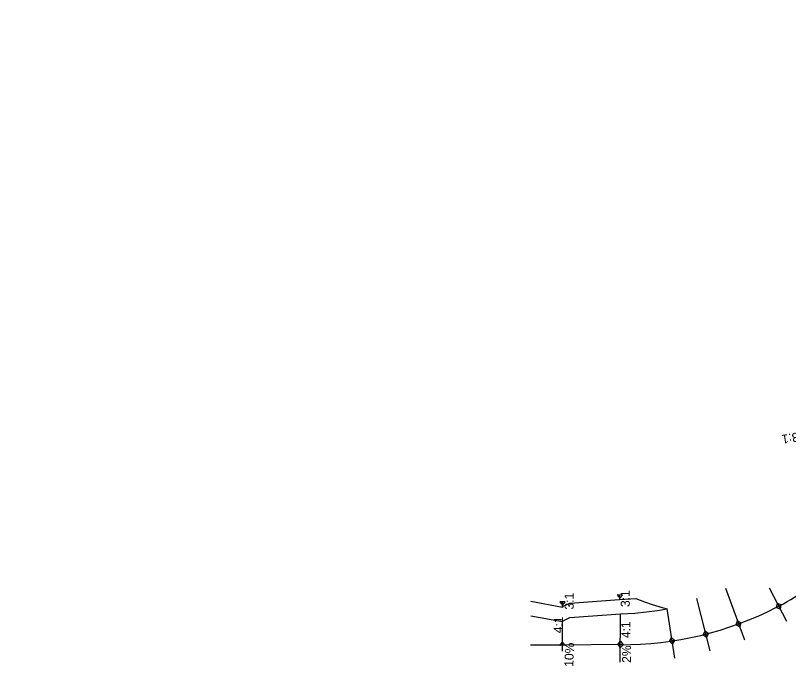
# Model space of a CAD drawing. Extents: x 2957411 to 5201395, y -5659629 to 3720102.
# Drawn here: x 5196292 to 5196826, y 3709360 to 3709819 of the extents above; entities that cross this region are included whole.
import ezdxf

# ---------------------------------------------------------------- set-up
doc = ezdxf.new("R2010")
doc.units = 0
for name, color, linetype in [('Default', 7, 'Continuous'), ('dsnProfileGradePropLine', 7, 'Continuous'), ('TES', 7, 'Continuous'), ('TL_Backslope', 7, 'Continuous')]:
    doc.layers.add(name, color=color, linetype=linetype)

msp = doc.modelspace()

# ---------------------------------------------------------------- linework, layer by layer
at = {"layer": 'dsnProfileGradePropLine'}
msp.add_arc((5196592.28, 3709519.5), 300, 6.5287, 6.5287, dxfattribs=at)
at = {"layer": 'TES'}
for p, q in [((5196795.72, 3709387.98), (5196782.63, 3709423.68)), ((5196824.85, 3709400.84), (5196812.73, 3709423.99)), ((5196709.54, 3709416.09), (5196709.44, 3709419.07)), ((5196771.85, 3709380.57), (5196762.61, 3709416.73)), ((5196669.89, 3709411.2), (5196669.91, 3709414.38)), ((5196817.75, 3709410.68), (5196817.75, 3709410.68)), ((5196709.78, 3709372.84), (5196709.88, 3709406.1)), ((5196747.36, 3709375.6), (5196742.25, 3709409.63)), ((5196669.8, 3709380.46), (5196669.87, 3709401.2)), ((5196669.81, 3709384.46), (5196647.92, 3709384.52)), ((5196709.82, 3709384.96), (5196669.82, 3709384.46))]:
    msp.add_line(p, q, dxfattribs=at)
for points in [[(5196669.9, 3709411.2), (5196675.07, 3709413.65), (5196709.37, 3709416.08), (5196720.59, 3709416.73), (5196726.49, 3709414.52), (5196731.79, 3709412.72), (5196738.67, 3709410.65), (5196742.32, 3709409.66)], [(5196669.9, 3709411.2), (5196669.89, 3709410.58), (5196648.01, 3709414.59)], [(5196669.87, 3709401.2), (5196669.87, 3709400.58), (5196647.98, 3709404.59)], [(5196669.87, 3709401.2), (5196674.87, 3709403.56), (5196709.88, 3709406.1), (5196719.82, 3709406.65), (5196727.9, 3709407.44), (5196735.51, 3709408.5), (5196742.25, 3709409.63)]]:
    msp.add_lwpolyline(points, dxfattribs=at)
for centre, radius, start, end in [((5196755.55, 3709533.87), 138, 297.7183, 317.5889), ((5196710.5, 3709620.34), 235.5, 269.8345, 297.0912)]:
    msp.add_arc(centre, radius, start, end, dxfattribs=at)
at = {"layer": 'TL_Backslope'}
for points in [[(5196709.43, 3709416.89), (5196711.39, 3709419.07), (5196707.65, 3709419.21)], [(5196669.9, 3709412.2), (5196671.86, 3709414.38), (5196668.12, 3709414.52)], [(5196818.23, 3709413.49), (5196820.93, 3709412.36), (5196817.61, 3709410.63)], [(5196820.33, 3709409.48), (5196820.94, 3709412.34), (5196817.62, 3709410.6)], [(5196790.81, 3709401.37), (5196793.35, 3709399.91), (5196789.83, 3709398.61)], [(5196792.37, 3709397.13), (5196793.35, 3709399.89), (5196789.83, 3709398.6)], [(5196768.32, 3709394.39), (5196770.7, 3709392.67), (5196767.06, 3709391.74)], [(5196745.24, 3709389.71), (5196747.43, 3709387.77), (5196743.72, 3709387.21)], [(5196769.44, 3709390.01), (5196770.7, 3709392.66), (5196767.07, 3709391.73)], [(5196669.82, 3709386.71), (5196671.77, 3709384.52), (5196668.02, 3709384.4)], [(5196709.81, 3709382.66), (5196711.77, 3709384.84), (5196708.02, 3709384.98)], [(5196710.05, 3709387.2), (5196711.77, 3709384.83), (5196708.03, 3709385.08)], [(5196745.91, 3709385.25), (5196747.43, 3709387.75), (5196743.73, 3709387.19)]]:
    msp.add_lwpolyline(points, close=True, dxfattribs=at)

# ---------------------------------------------------------------- texts
at = {"layer": 'Default'}
for s, rotation, p in [('3:1', 189.1928, (5196832.35, 3709531.49)), ('3:1', 90.1531, (5196716.34, 3709410.88)), ('3:1', 90.1531, (5196677.63, 3709409.12)), ('4:1', 88.05, (5196669.92, 3709392.66)), ('4:1', 90.1531, (5196716.74, 3709389.42)), ('10%', 87.9301, (5196677.38, 3709369.49)), ('2%', 90.1531, (5196717.25, 3709372.31))]:
    msp.add_text(s, height=6.24, rotation=rotation, dxfattribs=at).set_placement(p)

doc.saveas('drawing.dxf')
